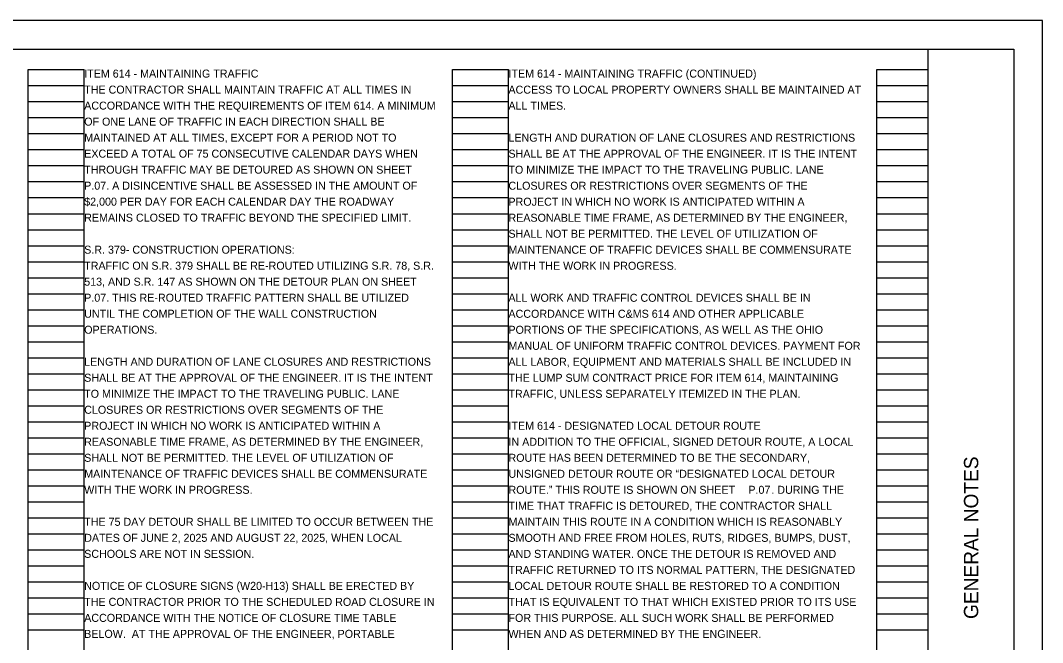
# Model space of a CAD drawing. Extents: x -59.3 to 34, y -1.2 to 22.
# Drawn here: x 16.13 to 34, y 11.12 to 22 of the extents above; entities that cross this region are included whole.
import ezdxf

# ---------------------------------------------------------------- set-up
doc = ezdxf.new("R2010")
doc.units = 0
for name, color, linetype in [('RD_P_Text', 7, 'Continuous'), ('SH_Border', 7, 'Continuous'), ('SH_Cut_Line', 7, 'Continuous'), ('SH_Data', 7, 'Continuous')]:
    doc.layers.add(name, color=color, linetype=linetype)

msp = doc.modelspace()

# ---------------------------------------------------------------- linework, layer by layer
at = {"layer": 'RD_P_Text'}
for p, q in [((16.26, 0.98), (16.26, 21.14)), ((16.26, 21.14), (17.24, 21.14)), ((17.24, 0.98), (17.24, 21.14)), ((23.68, 0.98), (23.68, 21.14)), ((23.68, 21.14), (24.66, 21.14)), ((24.66, 0.98), (24.66, 21.14)), ((31.1, 0.98), (31.1, 21.14)), ((31.1, 21.14), (32, 21.14)), ((32, 0.98), (32, 21.14)), ((16.26, 20.86), (17.24, 20.86)), ((23.68, 20.86), (24.66, 20.86)), ((31.1, 20.86), (32, 20.86)), ((16.26, 20.58), (17.24, 20.58)), ((23.68, 20.58), (24.66, 20.58)), ((31.1, 20.58), (32, 20.58)), ((16.26, 20.3), (17.24, 20.3)), ((23.68, 20.3), (24.66, 20.3)), ((31.1, 20.3), (32, 20.3)), ((16.26, 20.02), (17.24, 20.02)), ((23.68, 20.02), (24.66, 20.02)), ((31.1, 20.02), (32, 20.02)), ((16.26, 19.74), (17.24, 19.74)), ((23.68, 19.74), (24.66, 19.74)), ((31.1, 19.74), (32, 19.74)), ((16.26, 19.46), (17.24, 19.46)), ((23.68, 19.46), (24.66, 19.46)), ((31.1, 19.46), (32, 19.46)), ((16.26, 19.18), (17.24, 19.18)), ((23.68, 19.18), (24.66, 19.18)), ((31.1, 19.18), (32, 19.18)), ((16.26, 18.9), (17.24, 18.9)), ((23.68, 18.9), (24.66, 18.9)), ((31.1, 18.9), (32, 18.9)), ((16.26, 18.62), (17.24, 18.62)), ((23.68, 18.62), (24.66, 18.62)), ((31.1, 18.62), (32, 18.62)), ((16.26, 18.34), (17.24, 18.34)), ((23.68, 18.34), (24.66, 18.34)), ((31.1, 18.34), (32, 18.34)), ((16.26, 18.06), (17.24, 18.06)), ((23.68, 18.06), (24.66, 18.06)), ((31.1, 18.06), (32, 18.06)), ((16.26, 17.78), (17.24, 17.78)), ((23.68, 17.78), (24.66, 17.78)), ((31.1, 17.78), (32, 17.78)), ((16.26, 17.5), (17.24, 17.5)), ((23.68, 17.5), (24.66, 17.5)), ((31.1, 17.5), (32, 17.5)), ((16.26, 17.22), (17.24, 17.22)), ((23.68, 17.22), (24.66, 17.22)), ((31.1, 17.22), (32, 17.22)), ((16.26, 16.94), (17.24, 16.94)), ((23.68, 16.94), (24.66, 16.94)), ((31.1, 16.94), (32, 16.94)), ((16.26, 16.66), (17.24, 16.66)), ((23.68, 16.66), (24.66, 16.66)), ((31.1, 16.66), (32, 16.66)), ((16.26, 16.38), (17.24, 16.38)), ((23.68, 16.38), (24.66, 16.38)), ((31.1, 16.38), (32, 16.38)), ((16.26, 16.1), (17.24, 16.1)), ((23.68, 16.1), (24.66, 16.1)), ((31.1, 16.1), (32, 16.1)), ((16.26, 15.82), (17.24, 15.82)), ((23.68, 15.82), (24.66, 15.82)), ((31.1, 15.82), (32, 15.82)), ((16.26, 15.54), (17.24, 15.54)), ((23.68, 15.54), (24.66, 15.54)), ((31.1, 15.54), (32, 15.54)), ((16.26, 15.26), (17.24, 15.26)), ((23.68, 15.26), (24.66, 15.26)), ((31.1, 15.26), (32, 15.26)), ((16.26, 14.98), (17.24, 14.98)), ((23.68, 14.98), (24.66, 14.98)), ((31.1, 14.98), (32, 14.98)), ((16.26, 14.7), (17.24, 14.7)), ((23.68, 14.7), (24.66, 14.7)), ((31.1, 14.7), (32, 14.7)), ((16.26, 14.42), (17.24, 14.42)), ((23.68, 14.42), (24.66, 14.42)), ((31.1, 14.42), (32, 14.42)), ((16.26, 14.14), (17.24, 14.14)), ((23.68, 14.14), (24.66, 14.14)), ((31.1, 14.14), (32, 14.14)), ((16.26, 13.86), (17.24, 13.86)), ((23.68, 13.86), (24.66, 13.86)), ((31.1, 13.86), (32, 13.86)), ((16.26, 13.58), (17.24, 13.58)), ((23.68, 13.58), (24.66, 13.58)), ((31.1, 13.58), (32, 13.58)), ((16.26, 13.3), (17.24, 13.3)), ((23.68, 13.3), (24.66, 13.3)), ((31.1, 13.3), (32, 13.3)), ((16.26, 13.02), (17.24, 13.02)), ((23.68, 13.02), (24.66, 13.02)), ((31.1, 13.02), (32, 13.02)), ((16.26, 12.74), (17.24, 12.74)), ((23.68, 12.74), (24.66, 12.74)), ((31.1, 12.74), (32, 12.74)), ((16.26, 12.46), (17.24, 12.46)), ((23.68, 12.46), (24.66, 12.46)), ((31.1, 12.46), (32, 12.46)), ((16.26, 12.18), (17.24, 12.18)), ((23.68, 12.18), (24.66, 12.18)), ((31.1, 12.18), (32, 12.18)), ((16.26, 11.9), (17.24, 11.9)), ((23.68, 11.9), (24.66, 11.9)), ((31.1, 11.9), (32, 11.9)), ((16.26, 11.62), (17.24, 11.62)), ((23.68, 11.62), (24.66, 11.62)), ((31.1, 11.62), (32, 11.62)), ((16.26, 11.34), (17.24, 11.34)), ((23.68, 11.34), (24.66, 11.34)), ((31.1, 11.34), (32, 11.34))]:
    msp.add_line(p, q, dxfattribs=at)
at = {"layer": 'SH_Border'}
msp.add_line((32, 0.5), (32, 21.5), dxfattribs=at)
msp.add_lwpolyline([(1.5, 21.5), (33.5, 21.5), (33.5, 0.5), (1.5, 0.5)], close=True, dxfattribs=at)
at = {"layer": 'SH_Cut_Line'}
msp.add_lwpolyline([(0, 0), (34, 0), (34, 22), (0, 22)], close=True, dxfattribs=at)

# ---------------------------------------------------------------- texts
at = {"layer": 'RD_P_Text'}
for s, p in [('ITEM 614 - MAINTAINING TRAFFIC', (17.24, 21)), ('ITEM 614 - MAINTAINING TRAFFIC (CONTINUED)', (24.66, 21))]:
    msp.add_text(s, height=0.14, dxfattribs=at).set_placement(p)
msp.add_text('GENERAL NOTES', height=0.25, rotation=90, dxfattribs=at).set_placement((32.875, 11.531))
at = {"layer": 'SH_Data'}
for s, p in [('THE CONTRACTOR SHALL MAINTAIN TRAFFIC AT ALL TIMES IN ', (17.24, 20.72)), ('ACCESS TO LOCAL PROPERTY OWNERS SHALL BE MAINTAINED AT ', (24.659, 20.719)), ('ACCORDANCE WITH THE REQUIREMENTS OF ITEM 614. A MINIMUM ', (17.24, 20.44)), ('ALL TIMES.', (24.659, 20.439)), ('OF ONE LANE OF TRAFFIC IN EACH DIRECTION SHALL BE ', (17.24, 20.16)), ('MAINTAINED AT ALL TIMES, EXCEPT FOR A PERIOD NOT TO ', (17.24, 19.88)), ('LENGTH AND DURATION OF LANE CLOSURES AND RESTRICTIONS ', (24.659, 19.879)), ('EXCEED A TOTAL OF 75 CONSECUTIVE CALENDAR DAYS WHEN ', (17.24, 19.6)), ('SHALL BE AT THE APPROVAL OF THE ENGINEER. IT IS THE INTENT ', (24.659, 19.599)), ('THROUGH TRAFFIC MAY BE DETOURED AS SHOWN ON SHEET ', (17.24, 19.32)), ('TO MINIMIZE THE IMPACT TO THE TRAVELING PUBLIC. LANE ', (24.659, 19.319)), ('P.07. A DISINCENTIVE SHALL BE ASSESSED IN THE AMOUNT OF ', (17.24, 19.04)), ('CLOSURES OR RESTRICTIONS OVER SEGMENTS OF THE ', (24.659, 19.039)), ('$2,000 PER DAY FOR EACH CALENDAR DAY THE ROADWAY ', (17.24, 18.76)), ('PROJECT IN WHICH NO WORK IS ANTICIPATED WITHIN A ', (24.659, 18.759)), ('REMAINS CLOSED TO TRAFFIC BEYOND THE SPECIFIED LIMIT.', (17.24, 18.48)), ('REASONABLE TIME FRAME, AS DETERMINED BY THE ENGINEER, ', (24.659, 18.479)), ('SHALL NOT BE PERMITTED. THE LEVEL OF UTILIZATION OF ', (24.659, 18.199)), ('S.R. 379- CONSTRUCTION OPERATIONS:', (17.24, 17.92)), ('MAINTENANCE OF TRAFFIC DEVICES SHALL BE COMMENSURATE ', (24.659, 17.919)), ('TRAFFIC ON S.R. 379 SHALL BE RE-ROUTED UTILIZING S.R. 78, S.R. ', (17.24, 17.64)), ('WITH THE WORK IN PROGRESS.', (24.659, 17.639)), ('513, AND S.R. 147 AS SHOWN ON THE DETOUR PLAN ON SHEET ', (17.24, 17.36)), ('P.07. THIS RE-ROUTED TRAFFIC PATTERN SHALL BE UTILIZED ', (17.24, 17.08)), ('ALL WORK AND TRAFFIC CONTROL DEVICES SHALL BE IN ', (24.659, 17.079)), ('UNTIL THE COMPLETION OF THE WALL CONSTRUCTION ', (17.24, 16.8)), ('ACCORDANCE WITH C&MS 614 AND OTHER APPLICABLE ', (24.659, 16.799)), ('OPERATIONS. ', (17.24, 16.52)), ('PORTIONS OF THE SPECIFICATIONS, AS WELL AS THE OHIO ', (24.659, 16.519)), ('MANUAL OF UNIFORM TRAFFIC CONTROL DEVICES. PAYMENT FOR ', (24.659, 16.239)), ('LENGTH AND DURATION OF LANE CLOSURES AND RESTRICTIONS ', (17.24, 15.96)), ('ALL LABOR, EQUIPMENT AND MATERIALS SHALL BE INCLUDED IN ', (24.659, 15.959)), ('SHALL BE AT THE APPROVAL OF THE ENGINEER. IT IS THE INTENT ', (17.24, 15.68)), ('THE LUMP SUM CONTRACT PRICE FOR ITEM 614, MAINTAINING ', (24.659, 15.679)), ('TO MINIMIZE THE IMPACT TO THE TRAVELING PUBLIC. LANE ', (17.24, 15.4)), ('TRAFFIC, UNLESS SEPARATELY ITEMIZED IN THE PLAN.', (24.659, 15.399)), ('CLOSURES OR RESTRICTIONS OVER SEGMENTS OF THE ', (17.24, 15.12)), ('PROJECT IN WHICH NO WORK IS ANTICIPATED WITHIN A ', (17.24, 14.84)), ('ITEM 614 - DESIGNATED LOCAL DETOUR ROUTE', (24.66, 14.84)), ('REASONABLE TIME FRAME, AS DETERMINED BY THE ENGINEER, ', (17.24, 14.56)), ('IN ADDITION TO THE OFFICIAL, SIGNED DETOUR ROUTE, A LOCAL ', (24.66, 14.56)), ('SHALL NOT BE PERMITTED. THE LEVEL OF UTILIZATION OF ', (17.24, 14.28)), ('ROUTE HAS BEEN DETERMINED TO BE THE SECONDARY, ', (24.66, 14.28)), ('MAINTENANCE OF TRAFFIC DEVICES SHALL BE COMMENSURATE ', (17.24, 14)), ('UNSIGNED DETOUR ROUTE OR “DESIGNATED LOCAL DETOUR ', (24.66, 14)), ('WITH THE WORK IN PROGRESS.', (17.24, 13.72)), ('ROUTE.” THIS ROUTE IS SHOWN ON SHEET ', (24.66, 13.72)), ('P.07', (28.855, 13.72)), ('. DURING THE ', (29.257, 13.72)), ('TIME THAT TRAFFIC IS DETOURED, THE CONTRACTOR SHALL ', (24.66, 13.44)), ('THE 75 DAY DETOUR SHALL BE LIMITED TO OCCUR BETWEEN THE ', (17.24, 13.16)), ('MAINTAIN THIS ROUTE IN A CONDITION WHICH IS REASONABLY ', (24.66, 13.16)), ('DATES OF JUNE 2, 2025 AND AUGUST 22, 2025, WHEN LOCAL ', (17.24, 12.88)), ('SMOOTH AND FREE FROM HOLES, RUTS, RIDGES, BUMPS, DUST, ', (24.66, 12.88)), ('SCHOOLS ARE NOT IN SESSION. ', (17.24, 12.6)), ('AND STANDING WATER. ONCE THE DETOUR IS REMOVED AND ', (24.66, 12.6)), ('TRAFFIC RETURNED TO ITS NORMAL PATTERN, THE DESIGNATED ', (24.66, 12.32)), ('NOTICE OF CLOSURE SIGNS (W20-H13) SHALL BE ERECTED BY ', (17.24, 12.04)), ('LOCAL DETOUR ROUTE SHALL BE RESTORED TO A CONDITION ', (24.66, 12.04)), ('THE CONTRACTOR PRIOR TO THE SCHEDULED ROAD CLOSURE IN ', (17.24, 11.76)), ('THAT IS EQUIVALENT TO THAT WHICH EXISTED PRIOR TO ITS USE ', (24.66, 11.76)), ('ACCORDANCE WITH THE NOTICE OF CLOSURE TIME TABLE ', (17.24, 11.48)), ('FOR THIS PURPOSE. ALL SUCH WORK SHALL BE PERFORMED ', (24.66, 11.48)), ('BELOW.  AT THE APPROVAL OF THE ENGINEER, PORTABLE ', (17.24, 11.2)), ('WHEN AND AS DETERMINED BY THE ENGINEER.', (24.66, 11.2))]:
    msp.add_text(s, height=0.14, dxfattribs=at).set_placement(p)

doc.saveas('drawing.dxf')
